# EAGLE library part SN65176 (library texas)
DIFFERENTIAL BUS TRANSCEIVER Source: http://focus.ti.com .. sn65176b.pdf
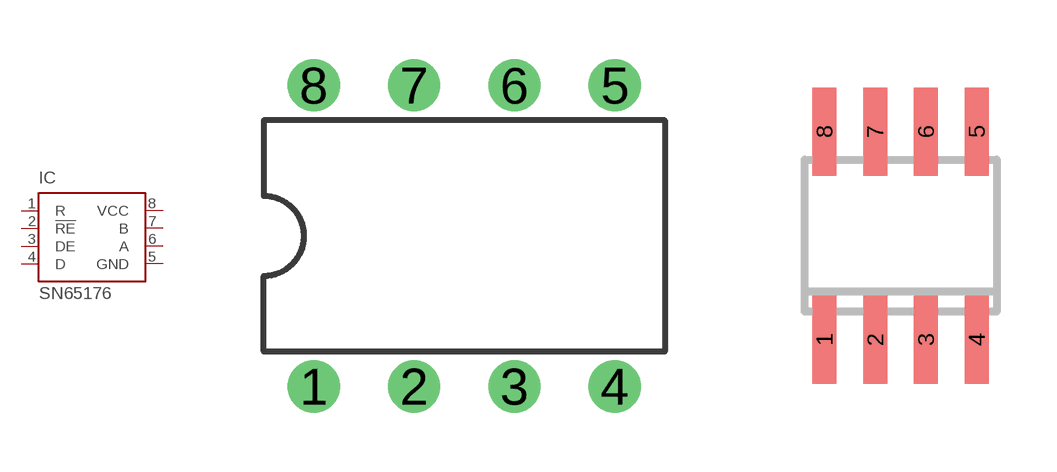
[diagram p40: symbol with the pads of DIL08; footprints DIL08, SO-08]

Designator prefix IC

## SN65176P (MF: TEXAS INSTRUMENTS; MPN: SN65176BP; OC_FARNELL: 1755024; OC_NEWARK: 60K6785)  [DIL08]
1  R  in
2  !RE  in
3  DE  in
4  D  in
5  GND  in
6  A  in
7  B  in
8  VCC  in

## SN65176D (MF: TEXAS INSTRUMENTS; MPN: SN65176BD; OC_FARNELL: 9589970; OC_NEWARK: 08F5891)  [SO-08]
Pads as for DIL08

## SN65176PS (OC_FARNELL: unknown; OC_NEWARK: unknown)  [SOP-08]
Pads as for DIL08

## Footprint DIL08 (pad centres in mm)
Dual In Line Package
drill 0.813 pad 1.27 round: 1 -3.81,-3.81; 2 -1.27,-3.81; 3 1.27,-3.81; 4 3.81,-3.81; 5 3.81,3.81; 6 1.27,3.81; 7 -1.27,3.81; 8 -3.81,3.81

## Footprint SO-08 (pad centres in mm)
D (R-PDSO-G8) Plastic Small Outline Package Source: http://focus.ti.com/lit/ds/symlink/sn65als176.pdf
smd 0.6 x 2.2: 1 -1.905,-2.6; 2 -0.635,-2.6; 3 0.635,-2.6; 4 1.905,-2.6; 5 1.905,2.6; 6 0.635,2.6; 7 -0.635,2.6; 8 -1.905,2.6

## Footprint SOP-08 (pad centres in mm)
PS (R-PDSO-G8) Source: http://focus.ti.com .. sn65176b.pdf
smd 0.6 x 2.2: 1 -1.905,-3.6; 2 -0.635,-3.6; 3 0.635,-3.6; 4 1.905,-3.6; 5 1.905,3.575; 6 0.635,3.575; 7 -0.635,3.575; 8 -1.905,3.575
